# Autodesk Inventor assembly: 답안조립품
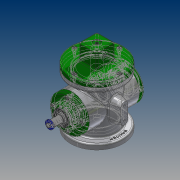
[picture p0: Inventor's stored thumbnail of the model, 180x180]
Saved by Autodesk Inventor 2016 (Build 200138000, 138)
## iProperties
Created: 2018-02
Part Number: 답안조립품
Material: 일반
Document SubType Name: Assembly
Designer: Administrator
Author: Administrator
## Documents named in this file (18)
- C:\Users\Administrator\Desktop\480207V1005\답안조립품.iam
- C:\Users\Administrator\Desktop\480207V1005\E-링.ipt
- C:\Users\Administrator\Desktop\480207V1005\V-벨트풀리.ipt
- C:\Users\Administrator\Desktop\480207V1005\덮개.ipt
- C:\Users\Administrator\Desktop\480207V1005\뒤커버.ipt
- C:\Users\Administrator\Desktop\480207V1005\링크.ipt
- C:\Users\Administrator\Desktop\480207V1005\베어링 17 x 40 x 12.ipt
- C:\Users\Administrator\Desktop\480207V1005\본체.ipt
- C:\Users\Administrator\Desktop\480207V1005\볼트 M4 x 8.ipt
- C:\Users\Administrator\Desktop\480207V1005\볼트 M4 x 10.ipt
- C:\Users\Administrator\Desktop\480207V1005\슬라이더.ipt
- C:\Users\Administrator\Desktop\480207V1005\앞커버.ipt
- C:\Users\Administrator\Desktop\480207V1005\오일 실 17 30 8.ipt
- C:\Users\Administrator\Desktop\480207V1005\와셔 4x16.ipt
- C:\Users\Administrator\Desktop\480207V1005\클레비스 핀 6 x 22.ipt
- 클레비스 핀 6 x 22.ipt
- C:\Users\Administrator\Desktop\480207V1005\키 4 x 4 x 12.ipt
- C:\Users\Administrator\Desktop\480207V1005\편심축.ipt
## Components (2 placed, 2 different names)
1. E-링:1
2. V-벨트풀리:1 — 각도:2
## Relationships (1: Angle 1)
- 각도:2 [Angle]: V-벨트풀리:1
